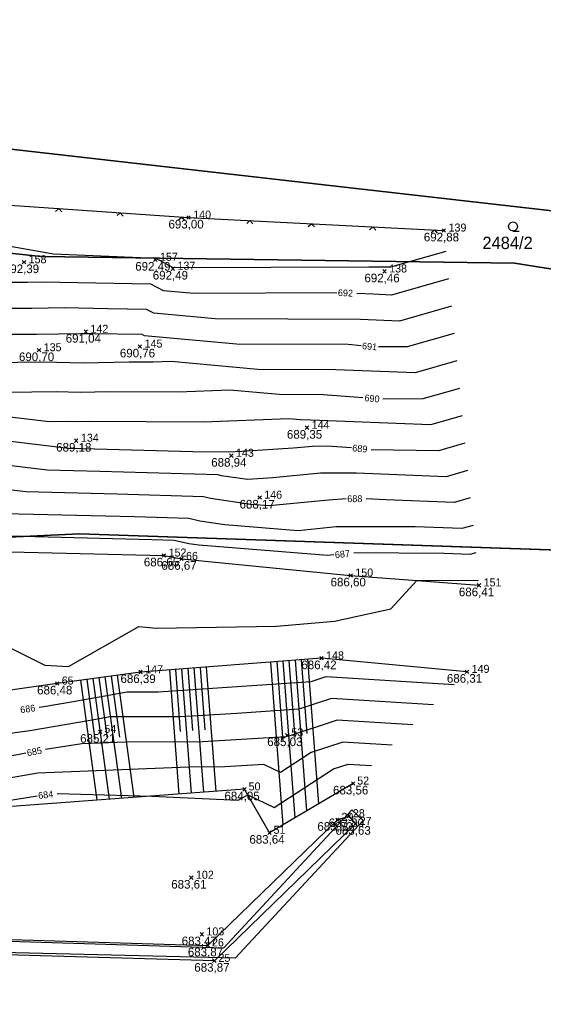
# Model space of a CAD drawing. Extents: x -439750 to -439180, y -1258684 to -1258308.
# Drawn here: x -439486.43 to -439469.39, y -1258511.26 to -1258479.7 of the extents above; entities that cross this region are included whole.
import ezdxf

# ---------------------------------------------------------------- set-up
doc = ezdxf.new("R2010")
doc.units = 0
for name, color, linetype in [('BODY', 7, 'Continuous'), ('CISBOD', 7, 'Continuous'), ('HRANA', 7, 'Continuous'), ('KATASTER', 7, 'Continuous'), ('POLOHOPIS', 7, 'Continuous'), ('SRAFY', 7, 'Continuous'), ('UOV', 7, 'Continuous'), ('VRSTEV', 7, 'Continuous'), ('VYSKY', 7, 'Continuous')]:
    doc.layers.add(name, color=color, linetype=linetype)

# ---------------------------------------------------------------- blocks, each defined once
blk = doc.blocks.new('304')
blk.add_lwpolyline([(0, 0), (-0.38, 0.1), (-0.65, 0.37), (-0.75, 0.74), (-0.65, 1.11), (-0.38, 1.38), (-0.01, 1.48), (0.36, 1.38), (0.63, 1.11), (0.73, 0.73), (0.63, 0.35), (0.36, 0.08), (-0.02, -0.02), (0.98, -0.02)])
blk = doc.blocks.new('KRIZEK')
for p, q in [((-2, 0), (2, 0)), ((0, 2), (0, -2))]:
    blk.add_line(p, q)
blk = doc.blocks.new('2123')
blk.add_lwpolyline([(-0.5, -0.5), (0, 0), (0.5, -0.5)])

msp = doc.modelspace()

# ---------------------------------------------------------------- linework, layer by layer
at = {"layer": 'HRANA'}
for points in [[(-439511.54, -1258493.8), (-439507.75, -1258495.43), (-439503.31, -1258496.25), (-439496.67, -1258496.69), (-439488.09, -1258496.97), (-439481.73, -1258497.12), (-439481.16, -1258497.23), (-439475.66, -1258497.77), (-439471.49, -1258498.09)], [(-439471.88, -1258500.9), (-439476.61, -1258500.46), (-439482.49, -1258500.91), (-439485.2, -1258501.28), (-439488.38, -1258501.74), (-439492.71, -1258501.52), (-439497.17, -1258500.51), (-439503.07, -1258499.91), (-439506.02, -1258500.06)], [(-439475.58, -1258504.53), (-439478.3, -1258506.13), (-439479.11, -1258504.72), (-439487.55, -1258505.34), (-439492.66, -1258505.61), (-439495.41, -1258504.44), (-439498.85, -1258504.36), (-439505, -1258503.79), (-439507.43, -1258504.94)]]:
    msp.add_lwpolyline(points, dxfattribs=at)
at = {"layer": 'KATASTER'}
for points in [[(-439462.74, -1258442.73), (-439465.13, -1258459.21), (-439469.01, -1258485.93), (-439514.85, -1258480.71), (-439509.68, -1258462.08), (-439512.86, -1258458.3), (-439516.51, -1258455.4), (-439520.66, -1258452.66), (-439525.5, -1258450.78), (-439531.73, -1258450.85), (-439536.69, -1258451.87), (-439541.07, -1258454.21), (-439546.64, -1258459.47)], [(-439546.64, -1258459.47), (-439541.07, -1258454.21), (-439536.69, -1258451.87), (-439531.73, -1258450.85), (-439525.5, -1258450.78), (-439520.66, -1258452.66), (-439516.51, -1258455.4), (-439512.86, -1258458.3), (-439509.68, -1258462.08), (-439514.85, -1258480.71), (-439515.19, -1258481.93), (-439503.22, -1258485.2), (-439495.92, -1258486.32), (-439485.72, -1258487.41), (-439470.33, -1258487.62), (-439429.22, -1258494.1), (-439415.96, -1258495.89), (-439399.97, -1258496.98), (-439400.54, -1258499.28), (-439484.47, -1258496.42), (-439507.21, -1258497.49), (-439520.19, -1258486.95), (-439538.17, -1258484.88), (-439548.5, -1258497.7)], [(-439548.5, -1258497.7), (-439538.17, -1258484.88), (-439520.19, -1258486.95), (-439507.21, -1258497.49), (-439484.47, -1258496.42), (-439400.54, -1258499.28), (-439387.09, -1258499.74), (-439411.19, -1258562.66), (-439413.56, -1258566.65), (-439437.77, -1258626.82), (-439438.12, -1258627.38), (-439482.75, -1258611.76), (-439518.67, -1258591.95), (-439550.54, -1258581.84), (-439567.51, -1258574.36), (-439597.45, -1258561.13)]]:
    msp.add_lwpolyline(points, dxfattribs=at)
for points in [[(-439515.19, -1258481.93), (-439514.85, -1258480.71), (-439469.01, -1258485.93), (-439399.61, -1258493.83), (-439399.2, -1258493.87), (-439399.97, -1258496.98), (-439415.96, -1258495.89), (-439429.22, -1258494.1), (-439470.33, -1258487.62), (-439485.72, -1258487.41), (-439495.92, -1258486.32), (-439503.22, -1258485.2)], [(-439543.31, -1258507.99), (-439510.11, -1258508.88), (-439509.96, -1258507.11), (-439505.22, -1258507.33), (-439505.26, -1258509.08), (-439479.78, -1258509.87), (-439475.62, -1258505.39), (-439475.25, -1258505.73), (-439479.41, -1258510.21), (-439505.77, -1258509.57), (-439505.73, -1258507.82), (-439509.5, -1258507.65), (-439509.65, -1258509.42), (-439543.32, -1258508.49)]]:
    msp.add_lwpolyline(points, close=True, dxfattribs=at)
at = {"layer": 'POLOHOPIS'}
msp.add_lwpolyline([(-439511.93, -1258482.54), (-439503.64, -1258483.68), (-439495.23, -1258484.84), (-439489.64, -1258485.55), (-439488, -1258485.65), (-439480.93, -1258486.14), (-439472.63, -1258486.56)], dxfattribs=at)
msp.add_lwpolyline([(-439475.72, -1258505.59), (-439475.5, -1258505.84), (-439480.09, -1258510.29), (-439489.89, -1258510.01), (-439489.9, -1258509.5), (-439480.3, -1258509.79), (-439476.09, -1258505.71)], close=True, dxfattribs=at)
at = {"layer": 'SRAFY'}
for p, q in [((-439477.068, -1258500.495), (-439476.708, -1258505.194)), ((-439481.154, -1258500.808), (-439480.845, -1258504.847)), ((-439480.955, -1258500.793), (-439480.8, -1258502.813)), ((-439480.755, -1258500.777), (-439480.446, -1258504.818)), ((-439480.556, -1258500.762), (-439480.401, -1258502.783)), ((-439480.357, -1258500.747), (-439480.047, -1258504.789)), ((-439478.264, -1258500.587), (-439477.86, -1258505.871)), ((-439478.065, -1258500.571), (-439477.866, -1258503.165)), ((-439477.865, -1258500.556), (-439477.476, -1258505.645)), ((-439477.666, -1258500.541), (-439477.475, -1258503.037)), ((-439477.466, -1258500.526), (-439477.092, -1258505.419)), ((-439477.267, -1258500.51), (-439477.083, -1258502.908)), ((-439484.043, -1258501.122), (-439483.508, -1258505.043)), ((-439483.845, -1258501.095), (-439483.576, -1258503.062)), ((-439483.647, -1258501.068), (-439483.108, -1258505.014)), ((-439483.449, -1258501.041), (-439483.178, -1258503.02)), ((-439483.251, -1258501.014), (-439482.708, -1258504.984)), ((-439481.553, -1258500.838), (-439481.244, -1258504.877)), ((-439481.354, -1258500.823), (-439481.199, -1258502.843)), ((-439484.439, -1258501.176), (-439483.908, -1258505.072)), ((-439484.241, -1258501.149), (-439483.974, -1258503.103))]:
    msp.add_line(p, q, dxfattribs=at)
at = {"layer": 'UOV'}
msp.add_lwpolyline([(-439484.47, -1258496.42), (-439507.21, -1258497.49), (-439513.68, -1258492.23), (-439512.62, -1258492.23), (-439510.04, -1258487.61), (-439512.85, -1258480.94), (-439399.2, -1258493.87), (-439444.59, -1258496.79), (-439457.07, -1258497.35)], close=True, dxfattribs=at)
at = {"layer": 'VRSTEV'}
for points in [[(-439472.563, -1258487.239), (-439474.364, -1258487.755), (-439475.068, -1258487.75), (-439481.431, -1258487.77), (-439481.982, -1258487.475), (-439485.316, -1258487.329), (-439486.733, -1258487.079), (-439487.567, -1258487.084), (-439488.686, -1258486.915), (-439489.699, -1258486.689), (-439490.553, -1258486.376), (-439494.362, -1258485.445), (-439494.481, -1258485.427), (-439495.169, -1258485.102), (-439495.299, -1258485.087), (-439496.141, -1258485.2), (-439497.343, -1258484.549)], [(-439472.387, -1258489.02), (-439474.074, -1258489.503), (-439475.335, -1258489.453), (-439480.066, -1258489.43), (-439482.054, -1258489.252), (-439482.296, -1258489.125), (-439483.548, -1258489.103), (-439484.957, -1258489.077), (-439486.022, -1258489.098), (-439487.975, -1258489.098), (-439490.426, -1258488.894), (-439491.279, -1258488.999), (-439492.179, -1258488.799), (-439494.568, -1258487.671), (-439495.977, -1258487.503), (-439499.186, -1258487.936), (-439500.286, -1258488.054), (-439501.945, -1258487.417), (-439503.99, -1258486.045)], [(-439476.105, -1258488.582), (-439480.759, -1258488.607), (-439481.744, -1258488.519), (-439482.151, -1258488.307), (-439482.769, -1258488.296), (-439485.7, -1258488.243), (-439486.167, -1258488.252), (-439487.024, -1258488.252), (-439491.41, -1258487.886), (-439491.566, -1258487.905), (-439491.73, -1258487.868), (-439494.869, -1258486.386), (-439495.638, -1258486.295), (-439497.956, -1258486.501)], [(-439472.475, -1258488.129), (-439474.328, -1258488.66), (-439474.93, -1258488.636), (-439475.458, -1258488.608)], [(-439475.314, -1258490.305), (-439475.741, -1258490.27), (-439479.372, -1258490.252), (-439482.364, -1258489.984), (-439482.442, -1258489.944), (-439484.031, -1258489.915), (-439484.276, -1258489.92), (-439484.437, -1258489.916), (-439485.877, -1258489.944), (-439488.927, -1258489.945), (-439489.442, -1258489.902), (-439490.993, -1258490.093), (-439492.627, -1258489.73), (-439494.268, -1258488.955), (-439496.033, -1258488.729)], [(-439472.211, -1258490.8), (-439473.567, -1258491.189), (-439476.146, -1258491.087), (-439478.679, -1258491.074), (-439481.498, -1258490.822), (-439482.08, -1258490.844), (-439482.855, -1258490.839), (-439484.36, -1258490.873), (-439485.63, -1258490.838), (-439488.18, -1258490.87), (-439489.085, -1258490.762), (-439490.69, -1258491.079), (-439490.995, -1258491.108), (-439491.403, -1258491.032), (-439493.076, -1258490.661), (-439493.968, -1258490.239), (-439496.655, -1258489.92), (-439498.128, -1258490.119), (-439500.255, -1258490.347), (-439500.914, -1258490.306), (-439501.983, -1258490.065), (-439503.965, -1258489.291)], [(-439472.299, -1258489.91), (-439473.821, -1258490.346), (-439474.751, -1258490.347)], [(-439475.26, -1258491.994), (-439476.551, -1258491.903), (-439477.986, -1258491.896), (-439479.582, -1258491.753), (-439481.265, -1258491.818), (-439483.507, -1258491.804), (-439484.443, -1258491.825), (-439485.233, -1258491.803), (-439486.819, -1258491.823), (-439488.956, -1258491.568), (-439490.352, -1258491.844), (-439491.592, -1258491.961), (-439493.255, -1258491.651), (-439493.524, -1258491.591), (-439493.668, -1258491.523), (-439495.465, -1258491.097)], [(-439472.035, -1258492.581), (-439473.06, -1258492.875), (-439476.956, -1258492.72), (-439477.292, -1258492.718), (-439477.666, -1258492.685), (-439480.451, -1258492.791), (-439484.16, -1258492.769), (-439484.526, -1258492.777), (-439484.836, -1258492.768), (-439485.457, -1258492.776), (-439488.827, -1258492.374), (-439490.015, -1258492.609), (-439492.189, -1258492.814), (-439493.159, -1258492.633), (-439494.463, -1258492.732), (-439496.81, -1258492.428), (-439497.202, -1258492.206), (-439497.639, -1258492.201), (-439500.78, -1258492.004), (-439502.49, -1258491.617)], [(-439472.123, -1258491.691), (-439473.313, -1258492.032), (-439474.61, -1258492.046)], [(-439471.859, -1258494.362), (-439472.552, -1258494.561), (-439475.47, -1258494.445), (-439476.642, -1258494.449), (-439478.185, -1258494.599), (-439479.016, -1258494.655), (-439479.854, -1258494.53), (-439479.962, -1258494.505), (-439483.814, -1258494.392), (-439485.521, -1258494.35), (-439488.568, -1258493.986), (-439489.34, -1258494.139), (-439491.593, -1258494.351), (-439493.625, -1258494.273), (-439495.736, -1258494.485), (-439497.018, -1258493.759), (-439500.331, -1258493.721), (-439500.645, -1258493.702), (-439500.816, -1258493.663), (-439501.939, -1258493.364), (-439504.272, -1258492.782)], [(-439475.638, -1258493.622), (-439476.42, -1258493.574), (-439476.901, -1258493.576), (-439477.533, -1258493.638), (-439479.183, -1258493.748), (-439479.636, -1258493.765), (-439480.795, -1258493.758), (-439484.379, -1258493.653), (-439484.827, -1258493.642), (-439488.698, -1258493.18), (-439489.677, -1258493.374), (-439492.539, -1258493.643), (-439492.819, -1258493.632), (-439495.489, -1258493.901), (-439497.11, -1258492.982), (-439498.985, -1258492.961), (-439499.291, -1258492.968)], [(-439471.947, -1258493.472), (-439472.806, -1258493.718), (-439474.99, -1258493.686)], [(-439475.803, -1258495.284), (-439476.384, -1258495.323), (-439478.305, -1258495.509), (-439478.903, -1258495.462), (-439480.211, -1258495.267), (-439480.441, -1258495.213), (-439483.25, -1258495.131), (-439486.215, -1258495.058), (-439488.439, -1258494.792), (-439489.002, -1258494.903), (-439490.646, -1258495.058), (-439494.432, -1258494.913), (-439495.983, -1258495.069), (-439496.926, -1258494.535), (-439498.974, -1258494.459)], [(-439471.682, -1258496.143), (-439472.045, -1258496.247), (-439473.568, -1258496.187), (-439476.126, -1258496.196), (-439477.361, -1258496.316), (-439479.751, -1258496.126), (-439480.567, -1258496.005), (-439480.92, -1258495.921), (-439482.685, -1258495.87), (-439486.909, -1258495.765), (-439488.31, -1258495.598), (-439488.665, -1258495.668), (-439489.7, -1258495.766), (-439495.238, -1258495.553), (-439496.231, -1258495.653), (-439496.834, -1258495.311), (-439498.649, -1258495.291), (-439501.869, -1258494.981), (-439503.527, -1258494.649)], [(-439471.771, -1258495.253), (-439472.298, -1258495.404), (-439474.519, -1258495.316), (-439475.152, -1258495.281)], [(-439476.205, -1258497.104), (-439476.417, -1258497.123), (-439480.599, -1258496.79), (-439480.924, -1258496.742), (-439481.399, -1258496.63), (-439482.121, -1258496.609), (-439487.603, -1258496.473), (-439488.181, -1258496.404), (-439488.327, -1258496.433), (-439488.754, -1258496.473), (-439496.044, -1258496.193), (-439496.478, -1258496.237), (-439496.741, -1258496.088), (-439497.535, -1258496.079), (-439498.767, -1258496.153)], [(-439503.263, -1258496.208), (-439501.764, -1258496.352), (-439498.297, -1258497.004), (-439498.836, -1258497.78), (-439497.141, -1258500.285), (-439495.396, -1258498.244), (-439489.878, -1258498.731), (-439488.236, -1258499.379), (-439485.601, -1258500.682), (-439484.832, -1258500.732), (-439482.541, -1258499.428), (-439481.974, -1258499.483), (-439478.072, -1258499.422), (-439476.185, -1258499.258), (-439474.352, -1258498.853), (-439473.51, -1258497.935), (-439471.667, -1258497.928), (-439471.537, -1258497.933), (-439471.506, -1258497.924)], [(-439471.594, -1258497.034), (-439471.791, -1258497.09), (-439472.618, -1258497.057), (-439475.556, -1258497.041)], [(-439486.215, -1258503.548), (-439486.548, -1258503.609), (-439488.253, -1258503.838), (-439488.921, -1258503.899), (-439491.202, -1258503.806), (-439492.242, -1258503.849), (-439493.533, -1258503.913), (-439494.708, -1258503.531), (-439495.925, -1258503.518), (-439497.432, -1258503.422), (-439498.301, -1258503.111), (-439499.194, -1258503.057), (-439501.492, -1258502.817), (-439504.585, -1258502.154), (-439505.364, -1258501.867), (-439506.52, -1258500.68), (-439507.651, -1258500.254), (-439507.661, -1258500.251), (-439508.349, -1258499.736)], [(-439485.785, -1258502.053), (-439485.635, -1258502.031), (-439484.675, -1258501.868), (-439482.924, -1258501.552), (-439481.922, -1258501.55), (-439481.112, -1258501.502), (-439476.946, -1258501.217), (-439476.459, -1258501.057), (-439472.3, -1258501.312)], [(-439472.971, -1258501.97), (-439476.279, -1258501.767), (-439477.346, -1258502.118), (-439479.358, -1258502.256), (-439481.2, -1258502.365), (-439483.476, -1258502.369), (-439484.124, -1258502.487), (-439486.091, -1258502.82), (-439488.573, -1258503.153), (-439488.773, -1258503.171), (-439490.59, -1258503.098), (-439492.221, -1258502.963), (-439493.057, -1258503.045), (-439493.956, -1258503.089), (-439494.284, -1258502.983), (-439496.235, -1258502.961), (-439496.691, -1258502.932), (-439498.015, -1258502.46), (-439499.374, -1258502.377), (-439499.76, -1258502.337), (-439501.704, -1258501.92), (-439504.249, -1258501.323)], [(-439473.642, -1258502.629), (-439476.099, -1258502.478), (-439477.672, -1258502.995), (-439477.767, -1258503.019), (-439480.477, -1258503.179), (-439482.961, -1258503.184), (-439484.393, -1258503.244), (-439485.578, -1258503.424)], [(-439474.313, -1258503.287), (-439475.919, -1258503.188), (-439476.948, -1258503.527), (-439477.942, -1258504.172), (-439478.477, -1258503.918), (-439479.754, -1258503.994), (-439480.926, -1258503.996), (-439485.832, -1258504.199), (-439487.005, -1258504.398), (-439487.932, -1258504.522), (-439489.068, -1258504.626), (-439489.814, -1258504.596), (-439492.445, -1258504.703), (-439493.109, -1258504.736), (-439495.131, -1258504.079), (-439495.614, -1258504.074), (-439498.172, -1258503.912), (-439498.588, -1258503.763), (-439499.015, -1258503.737), (-439503.223, -1258503.297)], [(-439485.201, -1258504.86), (-439482.128, -1258504.942), (-439479.32, -1258505.069), (-439479.005, -1258504.903), (-439478.15, -1258505.309), (-439476.223, -1258504.058), (-439475.74, -1258503.899), (-439474.984, -1258503.945)], [(-439495.042, -1258505.673), (-439493.082, -1258505.43), (-439492.686, -1258505.559), (-439492.647, -1258505.557), (-439492.281, -1258505.542), (-439487.986, -1258505.241), (-439487.612, -1258505.207), (-439487.461, -1258505.187), (-439487.271, -1258505.155), (-439485.85, -1258504.932)]]:
    msp.add_lwpolyline(points, dxfattribs=at)

# ---------------------------------------------------------------- block references
at = {"layer": 'BODY', "xscale": 0.04, "yscale": 0.04000000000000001, "rotation": 44.977187}
for p in [(-439480.93, -1258486.14), (-439472.63, -1258486.56), (-439486.28, -1258487.59), (-439482.01, -1258487.51), (-439481.44, -1258487.8), (-439474.56, -1258487.89), (-439484.27, -1258489.85), (-439485.79, -1258490.45), (-439482.51, -1258490.33), (-439477.08, -1258492.97), (-439484.58, -1258493.39), (-439479.54, -1258493.88), (-439478.62, -1258495.24), (-439481.73, -1258497.12), (-439481.16, -1258497.23), (-439475.66, -1258497.77), (-439471.49, -1258498.09), (-439476.61, -1258500.46), (-439482.49, -1258500.91), (-439471.88, -1258500.9), (-439485.2, -1258501.28), (-439483.8, -1258502.85), (-439477.72, -1258502.96), (-439479.11, -1258504.72), (-439475.58, -1258504.53), (-439475.72, -1258505.59), (-439476.09, -1258505.71), (-439475.5, -1258505.84), (-439478.3, -1258506.13), (-439480.84, -1258507.59), (-439480.5, -1258509.43), (-439480.3, -1258509.79), (-439480.09, -1258510.29)]:
    msp.add_blockref('KRIZEK', p, dxfattribs=at)
at = {"layer": 'KATASTER', "xscale": 0.2, "yscale": 0.20000000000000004}
msp.add_blockref('304', (-439470.381, -1258486.577), dxfattribs=at)
at = {"layer": 'POLOHOPIS'}
for p, xscale, yscale, rotation in [((-439485.142, -1258485.848), 0.19999999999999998, 0.2, -3.964026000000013), ((-439483.147, -1258485.986), 0.19999999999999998, 0.2, -3.964026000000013), ((-439481.152, -1258486.125), 0.19999999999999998, 0.2, -3.964026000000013), ((-439478.933, -1258486.241), 0.2, 0.19999999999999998, -2.8754059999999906), ((-439476.935, -1258486.342), 0.2, 0.19999999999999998, -2.8754059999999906), ((-439474.938, -1258486.443), 0.2, 0.19999999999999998, -2.8754059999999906), ((-439472.94, -1258486.544), 0.2, 0.19999999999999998, -2.8754059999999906)]:
    msp.add_blockref('2123', p, dxfattribs=dict(at, xscale=xscale, yscale=yscale, rotation=rotation))

# ---------------------------------------------------------------- texts
at = {"layer": 'CISBOD'}
for s, p in [('140', (-439480.778, -1258486.176)), ('139', (-439472.478, -1258486.596)), ('158', (-439486.128, -1258487.626)), ('157', (-439481.858, -1258487.546)), ('137', (-439481.288, -1258487.836)), ('138', (-439474.408, -1258487.926)), ('142', (-439484.118, -1258489.886)), ('135', (-439485.638, -1258490.486)), ('145', (-439482.358, -1258490.366)), ('144', (-439476.928, -1258493.006)), ('134', (-439484.428, -1258493.426)), ('143', (-439479.388, -1258493.916)), ('146', (-439478.468, -1258495.276)), ('152', (-439481.578, -1258497.156)), ('66', (-439481.012, -1258497.266)), ('150', (-439475.508, -1258497.806)), ('151', (-439471.338, -1258498.126)), ('148', (-439476.458, -1258500.496)), ('147', (-439482.338, -1258500.946)), ('149', (-439471.728, -1258500.936)), ('65', (-439485.052, -1258501.316)), ('54', (-439483.667, -1258502.886)), ('53', (-439477.587, -1258502.996)), ('50', (-439478.977, -1258504.756)), ('52', (-439475.447, -1258504.566)), ('29', (-439475.957, -1258505.746)), ('28', (-439475.587, -1258505.626)), ('27', (-439475.367, -1258505.876)), ('51', (-439478.167, -1258506.166)), ('102', (-439480.688, -1258507.626)), ('103', (-439480.348, -1258509.466)), ('26', (-439480.167, -1258509.826)), ('25', (-439479.957, -1258510.326))]:
    msp.add_text(s, height=0.26, dxfattribs=at).set_placement(p)
at = {"layer": 'KATASTER'}
msp.add_text('2484/2', height=0.4, dxfattribs=at).set_placement((-439471.377, -1258487.164))
at = {"layer": 'VRSTEV'}
for s, rotation, p in [('692', 357.708, (-439476.079, -1258488.691)), ('691', 355.531, (-439475.297, -1258490.418)), ('690', 355.073, (-439475.219, -1258492.108)), ('689', 354.442, (-439475.617, -1258493.734)), ('688', 0.229, (-439475.77, -1258495.389)), ('687', 5.787, (-439476.162, -1258497.21)), ('686', 8.089, (-439486.383, -1258502.25)), ('685', 11.173, (-439486.162, -1258503.651)), ('684', 6.313, (-439485.805, -1258505.035))]:
    msp.add_text(s, height=0.22, rotation=rotation, dxfattribs=at).set_placement(p)
at = {"layer": 'VYSKY'}
for s, p in [('693,00', (-439481.582, -1258486.496)), ('692,88', (-439473.282, -1258486.916)), ('692,39', (-439486.932, -1258487.946)), ('692,49', (-439482.662, -1258487.866)), ('692,49', (-439482.092, -1258488.156)), ('692,46', (-439475.212, -1258488.246)), ('691,04', (-439484.922, -1258490.206)), ('690,76', (-439483.162, -1258490.686)), ('690,70', (-439486.442, -1258490.806)), ('689,35', (-439477.732, -1258493.326)), ('689,18', (-439485.232, -1258493.746)), ('688,94', (-439480.192, -1258494.236)), ('688,17', (-439479.272, -1258495.596)), ('686,65', (-439482.382, -1258497.476)), ('686,67', (-439481.812, -1258497.586)), ('686,60', (-439476.312, -1258498.126)), ('686,41', (-439472.142, -1258498.446)), ('686,42', (-439477.262, -1258500.816)), ('686,39', (-439483.142, -1258501.266)), ('686,31', (-439472.532, -1258501.256)), ('686,48', (-439485.852, -1258501.636)), ('685,21', (-439484.452, -1258503.206)), ('685,03', (-439478.372, -1258503.316)), ('683,56', (-439476.232, -1258504.886)), ('684,05', (-439479.762, -1258505.076)), ('683,82', (-439476.742, -1258506.066)), ('683,80', (-439476.372, -1258505.946)), ('683,63', (-439476.152, -1258506.196)), ('683,64', (-439478.952, -1258506.486)), ('683,61', (-439481.492, -1258507.946)), ('683,47', (-439481.152, -1258509.786)), ('683,87', (-439480.952, -1258510.146)), ('683,87', (-439480.742, -1258510.646))]:
    msp.add_text(s, height=0.28, dxfattribs=at).set_placement(p)

doc.saveas('drawing.dxf')
